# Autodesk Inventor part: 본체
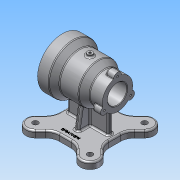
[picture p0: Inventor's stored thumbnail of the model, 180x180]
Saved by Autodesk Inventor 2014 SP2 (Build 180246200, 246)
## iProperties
Created: 2017-03
Part Number: 본체
Material: 알루미늄 6061
Document SubType Name: Modeling
Designer: 702
Density: 2.71 g/cm^3
Appearance: 알루미늄 - 평지
Mass: 1008.06 g
Surface Area: 842.103 cm^2
Volume: 371.977 cm^3
Author: 702
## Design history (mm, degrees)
sketch "스케치1"
  geometry: L1 (-50, 0)-(50, 0); L2 (-50, 0)-(-50, 45); L3 (-50, 45)-(-30, 45); L4 (-30, 45)-(-19, 36); L5 (-19, 36)-(15, 36); L6 (15, 36)-(27, 27.5); L7 (27, 27.5)-(50, 27.5); L8 (50, 27.5)-(50, 0); 2 further points
  constraints: 16 end point, 3 parallel, 2 perpendicular, 1 coincident, 1 horizontal, 1 midpoint
  dimensions: "d0" = 100 distance of L1.start L1.end; "d1" = 20 distance of L2.end L3.end; "d3" = 90 diameter of L3 L1; "d4" = 72 diameter of L5 L1; "d5" = 55 diameter of L7 L1; "d6" = 31 horizontal distance of L2.end L4.end; "d7" = 65 horizontal distance of L2.end L5.end; "d8" = 23 distance of L7.end L6.end
revolve "회전1" sketch "스케치1" stored, may be unused: angle "d9" = 90 deg
sketch "스케치2"
  geometry: C1 r 45 at (0, 0) reference
hole "구멍1" sketch "스케치2" at (0, 0) diameter "d10" = 52; stored, may be unused: countersink angle "d14" = 90 deg, drill point angle "d16" = 0 deg; dims "d11" = 6, "d12" = 70, "d13" = 23, "d15" = 70
sketch "스케치3"
  geometry: C1 r 26 at (0, 0) reference
hole "구멍2" sketch "스케치3" at (0, 0) diameter "d17" = 35; stored, may be unused: countersink angle "d21" = 90 deg, drill point angle "d23" = 118 deg; dims "d18" = 6, "d19" = 70, "d20" = 23, "d22" = 70
node "작업 평면1"
sketch "스케치4"
  geometry: L1 (45, 45)-(-45, 45); L2 (-45, 45)-(-45, -45); L3 (-45, -45)-(20.958, -45); L4 (45, -20.958)-(45, 45); L5 (45, 45)-(-45, -45); L6 (-45, 45)-(49.497, -49.497); L7 (45, 0)-(-45, 0); L8 (61.518, -37.477)-(37.477, -61.518); L9 (37.477, -61.518)-(20.958, -45); L10 (61.518, -37.477)-(45, -20.958); A1 r 70 centre (0, 0) between (49.497, -49.497) and (59.97, -36.106); A2 r 17 centre (49.497, -49.497) between (36.106, -59.97) and (59.97, -36.106); 3 further points
  constraints: 20 end point, 7 point on circle, 5 midpoint, 4 perpendicular, 3 coincident, 3 parallel, 3 tangent, 2 centre point, 2 point on line, 1 horizontal
  dimensions: "d26" = 90 distance of L2.end L1.end; "d27" = 140 diameter of A1; "d28" = 90 distance between parallel lines of L2 L4; "d30" = 45 deg angle of L7 L6; "d103" = 34 diameter of A2
extrude "돌출1" join sketch "스케치4" distance "d31" = 12; taper "d32" = 0 deg
fillet "모깎기1" dims "d36" = 25
sketch "스케치5"
  geometry: L1 (-37, -4)-(37, -4); L2 (37, -4)-(37, 4); L3 (37, 4)-(-37, 4); L4 (-37, 4)-(-37, -4); L5 (-37, -4)-(37, 4); L6 (37, -4)-(-37, 4); 1 further point
  constraints: 12 end point, 2 midpoint, 2 parallel, 1 horizontal, 1 perpendicular
  dimensions: "d37" = 74 distance of L3.end L2.end; "d38" = 8 distance of L2.end L1.end
extrude "돌출2" join sketch "스케치5" stored distance "d39" = 12; taper "d40" = 0 deg
sketch "스케치6"
  geometry: L1 (-70, 25)-(-31.096, 18.14); L2 (-70, 37.477)-(-70, 66.497) reference; L3 (-70, 28.281)-(-70, 37.477) reference; A1 r 36 centre (0, 0) between (-35.777, -4) and (-35.777, 4) reference; 2 further points
  constraints: 2 end point, 1 point on circle, 1 point on line
  dimensions: "d41" = 25 vertical distance of point (0, 0) L1.start; "d104" = 100 deg angle of L2 L1
feature "리브1" sketch "스케치6" dims "d43" = 1, "d44" = 8, "d45" = 0, "d46" = 0, "d47" = 1, "d48" = 1
sketch "스케치7"
  geometry: C1 r 7 at (0, 27.5); 2 further points
  constraints: 2 vertical alignment, 1 centre point, 1 other
  dimensions: "d49" = 14 diameter of C1
extrude "돌출3" join sketch "스케치7" distance "d50" = 15; taper "d51" = 0 deg
sketch "스케치8"
  geometry: A1 r 7 centre (0, 0) between (6.943, -0.891) and (-6.943, -0.891) reference; A2 r 7 centre (-23.816, -41.25) between (-26.516, -34.792) and (-19.573, -46.817) reference; A3 r 7 centre (23.816, -41.25) between (19.573, -46.817) and (26.516, -34.792) reference
hole "구멍3" sketch "스케치8" at (0, 0), (-23.816, -41.25), (23.816, -41.25) diameter "d55" = 3.242; stored, may be unused: countersink angle "d59" = 90 deg, drill point angle "d61" = 118 deg; dims "d56" = 9, "d57" = 70, "d58" = 23, "d60" = 11
sketch "스케치9"
  geometry: 2 further points
  constraints: 1 vertical alignment
  dimensions: "d62" = 40 distance of point (0, 0) point (0, 40)
hole "구멍4" sketch "스케치9" at (0, 40) diameter "d63" = 3.242; stored, may be unused: countersink angle "d67" = 90 deg, drill point angle "d69" = 118 deg; dims "d64" = 9, "d65" = 70, "d66" = 23, "d68" = 11
node "작업 평면2"
sketch "스케치10"
  geometry: C1 r 5 at (0, 0); 1 further point
  constraints: 1 centre point, 1 coincident
  dimensions: "d74" = 10 diameter of C1
extrude "돌출4" join sketch "스케치10" stored distance "d75" = 10; taper "d76" = 0 deg
sketch "스케치11"
  geometry: C1 r 5 at (0, 0) reference
hole "구멍5" sketch "스케치11" at (0, 0) diameter "d77" = 4.134; stored, may be unused: countersink angle "d81" = 90 deg, drill point angle "d83" = 118 deg; dims "d78" = 9, "d79" = 70, "d80" = 23, "d82" = 11
sketch "스케치12"
  geometry: L1 (45, -10.603)-(45, 10.603) reference; 5 further points
  constraints: 1 other
  dimensions: "d84" = 35 distance of point (0, -35) point (0, 0); "d85" = 45 distance from line of L1 point (0, -35)
feature "엠보싱1" sketch "스케치12" dims "d86" = 0.5, "d87" = 0
chamfer "모따기1" distance "d88" = 1; stored, may be unused: second distance "d89" = 2, angle "d90" = 45 deg
fillet "모깎기2" dims "d91" = 3
fillet "모깎기3" dims "d92" = 3
fillet "모깎기4" dims "d93" = 1
fillet "모깎기5" dims "d94" = 3
fillet "모깎기6" dims "d95" = 3
sketch "스케치14"
  geometry: A1 r 14 centre (49.497, 49.497) between (59.397, 39.598) and (39.598, 59.397) reference; A2 r 14 centre (-49.497, 49.497) between (-39.598, 59.397) and (-59.397, 39.598) reference; A3 r 14 centre (-49.497, -49.497) between (-59.397, -39.598) and (-39.598, -59.397) reference; A4 r 14 centre (49.497, -49.497) between (39.598, -59.397) and (59.397, -39.598) reference; 1 further point
hole "구멍7" sketch "스케치14" at (-49.497, -49.497), (49.497, -49.497), (49.497, 49.497), (-49.497, 49.497) diameter "d105" = 10; stored, may be unused: countersink angle "d109" = 90 deg, drill point angle "d111" = 118 deg; dims "d106" = 6, "d107" = 4, "d108" = 2, "d110" = 8
node "솔리드1"
pattern_circular "원형 패턴1" dims angle "d34" = 360 deg
mirror "대칭1"
pattern_circular "원형 패턴2" dims angle "d53" = 360 deg
pattern_circular "원형 패턴3" dims angle "d71" = 360 deg
other parameters: "d24" = -82
